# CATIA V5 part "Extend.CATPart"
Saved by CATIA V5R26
Part number: Extend
Bounding box of the stored display mesh (mm): x 864.508 to 1986.261, y -737.566 to -597.634, z 414.34 to 666.679
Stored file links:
  D:\LinkedIn Learning\NURBS\CATIA\Class Parts\Extend.CATPart
  D:\LinkedIn Learning\NURBS\CATIA\Class Parts\Arm_Rest-Step-2.CATPart
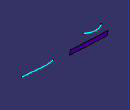
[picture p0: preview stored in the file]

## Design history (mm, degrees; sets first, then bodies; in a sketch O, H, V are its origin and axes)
AxisSystem1: origin (0, 0, 0), X (1, 0, 0), Y (0, 1, 0), Z (0, 0, 1)
Set1
  DatumSurface1
  DatumCurve1
  St3DCurveFeature1 "CATSt3DCurveFeatureName": Order 6, CreationType 1, ClosureMode false, ConstructionPoints ({point type Coord, X 1241.6055, Y -629.8993, Z 666.6793}; {point type Coord, X 1175.9236, Y -637.8441, Z 619.4966}; {point type Coord, X 1090.2018, Y -563.3732, Z 650.0578}; {point type Coord, X 1013.537, Y -617.5116, Z 664.4539}), SymmetryMode false
Body1 (main body)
